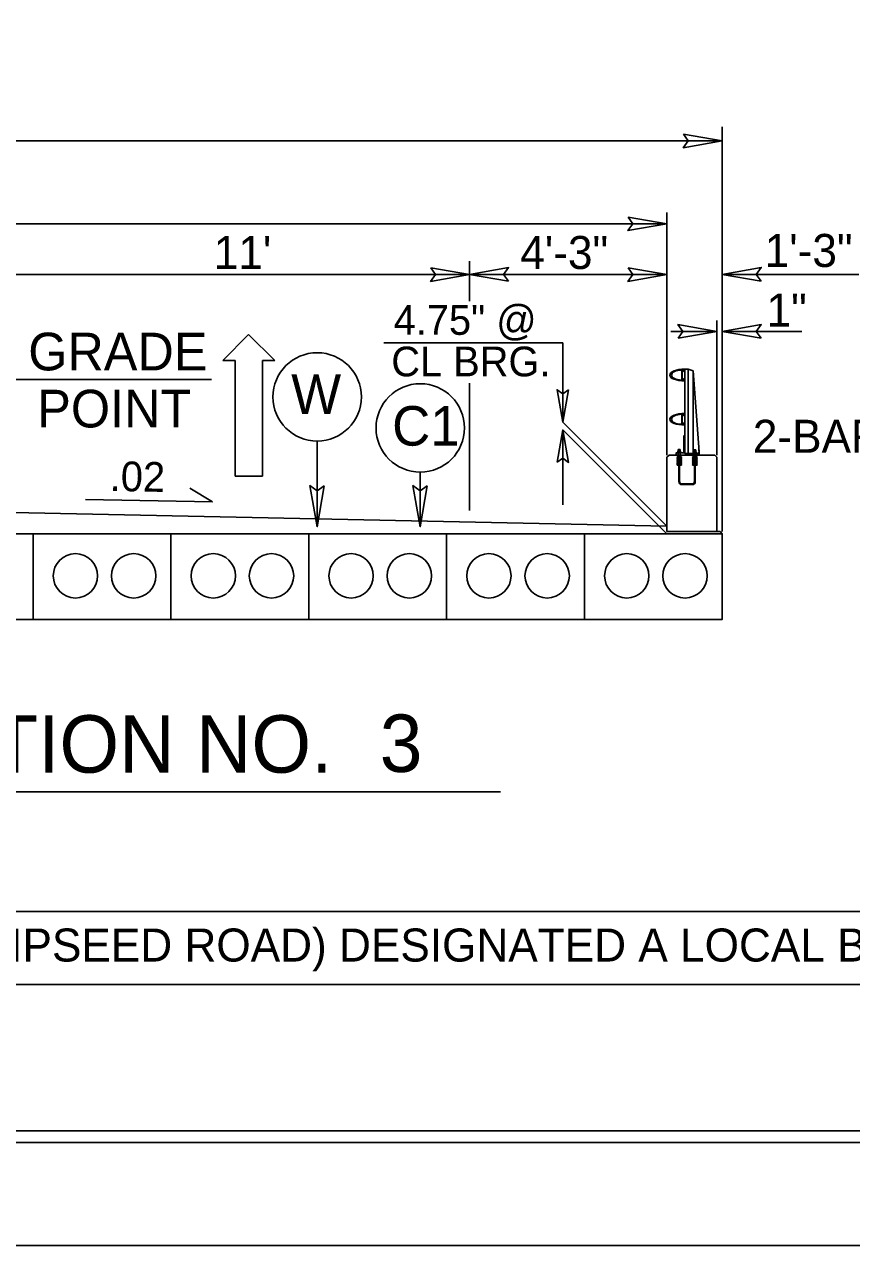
# Model space of a CAD drawing. Extents: x 693533 to 693723, y 486383 to 486493.
# Drawn here: x 693619.39 to 693637.39, y 486383.31 to 486409.89 of the extents above; entities that cross this region are included whole.
import ezdxf

# ---------------------------------------------------------------- set-up
doc = ezdxf.new("R2010")
doc.units = 0
for name, color, linetype in [('Old_Level_1', 7, 'Continuous'), ('Old_Level_28', 7, 'Continuous'), ('Old_Level_3', 7, 'Continuous'), ('Prop Dimension', 7, 'Continuous'), ('Prop Lane Arrow CELL', 7, 'Continuous'), ('Sheet Cutting Line CELL', 7, 'Continuous'), ('Sheet Plot Border Inside CELL', 7, 'Continuous'), ('Sheet Plot Border Outside CELL', 7, 'Continuous'), ('Sheet Typical CELL', 7, 'Continuous'), ('Typical Bridge Rail Two Bar CELL', 7, 'Continuous'), ('Typical ID Circle CELL', 7, 'Continuous'), ('Typical Pavement Slope Information CELL', 7, 'Continuous'), ('Typical Terminator CELL', 7, 'Continuous'), ('Typical Text ID Circle CELL', 7, 'Continuous')]:
    doc.layers.add(name, color=color, linetype=linetype)

msp = doc.modelspace()

# ---------------------------------------------------------------- linework, layer by layer
at = {"layer": 'Old_Level_1'}
msp.add_line((693607.128, 486393.188), (693629.755, 486393.188), dxfattribs=at)
msp.add_lwpolyline([(693595.018, 486390.588), (693644.204, 486390.588), (693644.204, 486388.993), (693595.018, 486388.993)], close=True, dxfattribs=at)
at = {"layer": 'Old_Level_28'}
for p, q in [((693634.581, 486398.856), (693634.581, 486407.663)), ((693601.581, 486407.359), (693634.581, 486407.359)), ((693633.374, 486400.52), (693633.374, 486405.801)), ((693602.787, 486405.557), (693633.374, 486405.557)), ((693629.081, 486403.872), (693629.081, 486404.74)), ((693618.081, 486404.451), (693629.081, 486404.451)), ((693629.081, 486404.451), (693633.374, 486404.451)), ((693634.581, 486404.454), (693637.549, 486404.454)), ((693634.464, 486400.52), (693634.464, 486403.447)), ((693634.464, 486403.211), (693633.46, 486403.211)), ((693634.581, 486403.211), (693636.31, 486403.211)), ((693619.016, 486402.168), (693623.462, 486402.168)), ((693629.081, 486399.312), (693629.081, 486402.086)), ((693618.081, 486399.291), (693633.374, 486398.972))]:
    msp.add_line(p, q, dxfattribs=at)
for points in [[(693633.737, 486407.504), (693634.581, 486407.359), (693633.732, 486407.209), (693633.84, 486407.359)], [(693632.53, 486405.702), (693633.374, 486405.557), (693632.526, 486405.407), (693632.633, 486405.557)], [(693628.237, 486404.596), (693629.081, 486404.451), (693628.232, 486404.301), (693628.34, 486404.451)], [(693629.924, 486404.305), (693629.081, 486404.451), (693629.929, 486404.601), (693629.821, 486404.451)], [(693632.53, 486404.596), (693633.374, 486404.451), (693632.526, 486404.301), (693632.633, 486404.451)], [(693635.424, 486404.308), (693634.581, 486404.454), (693635.429, 486404.604), (693635.321, 486404.454)], [(693633.62, 486403.066), (693634.464, 486403.211), (693633.615, 486403.361), (693633.723, 486403.211)], [(693635.424, 486403.066), (693634.581, 486403.211), (693635.429, 486403.361), (693635.321, 486403.211)], [(693616.581, 486398.804), (693619.581, 486398.804), (693619.581, 486396.944), (693616.581, 486396.944)], [(693619.581, 486398.804), (693622.581, 486398.804), (693622.581, 486396.944), (693619.581, 486396.944)], [(693622.581, 486398.804), (693625.581, 486398.804), (693625.581, 486396.944), (693622.581, 486396.944)], [(693625.581, 486398.804), (693628.581, 486398.804), (693628.581, 486396.944), (693625.581, 486396.944)], [(693628.581, 486398.804), (693631.581, 486398.804), (693631.581, 486396.944), (693628.581, 486396.944)], [(693631.581, 486398.804), (693634.581, 486398.804), (693634.581, 486396.944), (693631.581, 486396.944)]]:
    msp.add_lwpolyline(points, close=True, dxfattribs=at)
for centre in [(693620.501, 486397.892), (693621.769, 486397.892), (693623.501, 486397.892), (693624.769, 486397.892), (693626.501, 486397.892), (693627.769, 486397.892), (693629.501, 486397.892), (693630.769, 486397.892), (693632.501, 486397.892), (693633.769, 486397.892)]:
    msp.add_circle(centre, 0.483, dxfattribs=at)
at = {"layer": 'Prop Dimension'}
for p, q in [((693627.211, 486402.962), (693631.109, 486402.962)), ((693631.109, 486401.237), (693631.109, 486402.962)), ((693631.109, 486401.237), (693633.374, 486398.972)), ((693631.109, 486401.069), (693633.374, 486398.804)), ((693631.109, 486401.069), (693631.109, 486399.439))]:
    msp.add_line(p, q, dxfattribs=at)
at = {"layer": 'Prop Lane Arrow CELL'}
for p, q in [((693623.709, 486402.58), (693624.267, 486403.147)), ((693624.267, 486403.147), (693624.843, 486402.58)), ((693623.979, 486402.58), (693623.709, 486402.58)), ((693623.979, 486400.06), (693623.979, 486402.58)), ((693624.843, 486402.58), (693624.573, 486402.58)), ((693624.573, 486402.58), (693624.573, 486400.06)), ((693624.573, 486400.06), (693623.979, 486400.06))]:
    msp.add_line(p, q, dxfattribs=at)
at = {"layer": 'Sheet Cutting Line CELL'}
msp.add_line((693532.659, 486383.314), (693701.059, 486383.314), dxfattribs=at)
at = {"layer": 'Sheet Plot Border Inside CELL'}
msp.add_lwpolyline([(693700.609, 486491.069), (693533.959, 486491.069), (693533.959, 486385.559), (693700.609, 486385.559)], close=True, dxfattribs=at)
at = {"layer": 'Sheet Plot Border Outside CELL'}
msp.add_lwpolyline([(693701.059, 486493.314), (693532.659, 486493.314), (693532.659, 486383.314), (693701.059, 486383.314)], close=True, dxfattribs=at)
at = {"layer": 'Sheet Typical CELL'}
msp.add_lwpolyline([(693699.359, 486490.814), (693549.359, 486490.814), (693549.359, 486385.814), (693699.359, 486385.814)], close=True, dxfattribs=at)
at = {"layer": 'Typical Bridge Rail Two Bar CELL'}
for p, q in [((693633.701, 486402.362), (693633.701, 486402.262)), ((693633.763, 486402.392), (693633.836, 486402.392)), ((693633.763, 486400.557), (693633.763, 486402.392)), ((693633.947, 486402.356), (693633.836, 486402.392)), ((693633.836, 486400.557), (693633.836, 486402.392)), ((693633.947, 486400.557), (693633.947, 486402.356)), ((693633.947, 486402.356), (693634.075, 486400.593)), ((693633.701, 486402.162), (693633.701, 486402.262)), ((693633.947, 486401.514), (693633.951, 486401.514)), ((693633.701, 486401.4), (693633.701, 486401.3)), ((693633.701, 486401.2), (693633.701, 486401.3)), ((693633.422, 486400.52), (693633.374, 486400.472)), ((693633.374, 486400.472), (693633.374, 486398.856)), ((693633.422, 486400.52), (693634.416, 486400.52)), ((693633.596, 486400.485), (693633.693, 486400.485)), ((693633.596, 486400.474), (693633.693, 486400.474)), ((693633.596, 486400.441), (693633.636, 486400.441)), ((693633.596, 486400.43), (693633.636, 486400.43)), ((693633.617, 486400.463), (693633.636, 486400.463)), ((693633.617, 486400.452), (693633.636, 486400.452)), ((693633.617, 486400.419), (693633.636, 486400.419)), ((693633.617, 486400.409), (693633.636, 486400.409)), ((693633.62, 486400.485), (693633.62, 486400.566)), ((693633.622, 486400.606), (693633.622, 486400.64)), ((693633.622, 486400.64), (693633.664, 486400.64)), ((693633.636, 486400.463), (693633.652, 486400.463)), ((693633.636, 486400.463), (693633.636, 486399.946)), ((693633.652, 486400.463), (693633.671, 486400.463)), ((693633.652, 486400.463), (693633.652, 486399.946)), ((693633.652, 486400.452), (693633.671, 486400.452)), ((693633.652, 486400.441), (693633.693, 486400.441)), ((693633.652, 486400.43), (693633.693, 486400.43)), ((693633.652, 486400.419), (693633.671, 486400.419)), ((693633.652, 486400.409), (693633.671, 486400.409)), ((693633.664, 486400.64), (693633.664, 486400.606)), ((693633.666, 486400.485), (693633.666, 486400.566)), ((693633.935, 486400.485), (693634.033, 486400.485)), ((693633.935, 486400.474), (693634.033, 486400.474)), ((693633.935, 486400.441), (693633.976, 486400.441)), ((693633.935, 486400.43), (693633.976, 486400.43)), ((693633.957, 486400.463), (693633.976, 486400.463)), ((693633.957, 486400.452), (693633.976, 486400.452)), ((693633.957, 486400.419), (693633.976, 486400.419)), ((693633.957, 486400.409), (693633.976, 486400.409)), ((693633.962, 486400.596), (693633.962, 486400.631)), ((693633.962, 486400.631), (693634.003, 486400.631)), ((693633.962, 486400.475), (693633.962, 486400.557)), ((693633.976, 486400.463), (693633.992, 486400.463)), ((693633.976, 486400.463), (693633.976, 486399.946)), ((693633.992, 486400.463), (693634.011, 486400.463)), ((693633.992, 486400.463), (693633.992, 486399.946)), ((693633.992, 486400.452), (693634.011, 486400.452)), ((693633.992, 486400.441), (693634.033, 486400.441)), ((693633.992, 486400.43), (693634.033, 486400.43)), ((693633.992, 486400.419), (693634.011, 486400.419)), ((693633.992, 486400.409), (693634.011, 486400.409)), ((693634.003, 486400.631), (693634.003, 486400.596)), ((693634.004, 486400.475), (693634.004, 486400.557)), ((693634.072, 486400.614), (693634.072, 486400.646)), ((693634.075, 486400.557), (693634.075, 486400.593)), ((693634.464, 486400.472), (693634.416, 486400.52)), ((693634.464, 486400.472), (693634.464, 486398.856)), ((693633.596, 486400.398), (693633.636, 486400.398)), ((693633.596, 486400.387), (693633.636, 486400.387)), ((693633.596, 486400.355), (693633.636, 486400.355)), ((693633.596, 486400.344), (693633.636, 486400.344)), ((693633.596, 486400.311), (693633.636, 486400.311)), ((693633.596, 486400.301), (693633.636, 486400.301)), ((693633.617, 486400.376), (693633.636, 486400.376)), ((693633.617, 486400.365), (693633.636, 486400.365)), ((693633.617, 486400.333), (693633.636, 486400.333)), ((693633.617, 486400.322), (693633.636, 486400.322)), ((693633.652, 486400.398), (693633.693, 486400.398)), ((693633.652, 486400.387), (693633.693, 486400.387)), ((693633.652, 486400.376), (693633.671, 486400.376)), ((693633.652, 486400.365), (693633.671, 486400.365)), ((693633.652, 486400.355), (693633.693, 486400.355)), ((693633.652, 486400.344), (693633.693, 486400.344)), ((693633.652, 486400.333), (693633.671, 486400.333)), ((693633.652, 486400.322), (693633.671, 486400.322)), ((693633.652, 486400.311), (693633.693, 486400.311)), ((693633.652, 486400.301), (693633.693, 486400.301)), ((693633.935, 486400.398), (693633.976, 486400.398)), ((693633.935, 486400.387), (693633.976, 486400.387)), ((693633.935, 486400.355), (693633.976, 486400.355)), ((693633.935, 486400.344), (693633.976, 486400.344)), ((693633.935, 486400.311), (693633.976, 486400.311)), ((693633.935, 486400.301), (693633.976, 486400.301)), ((693633.957, 486400.376), (693633.976, 486400.376)), ((693633.957, 486400.365), (693633.976, 486400.365)), ((693633.957, 486400.333), (693633.976, 486400.333)), ((693633.957, 486400.322), (693633.976, 486400.322)), ((693633.992, 486400.398), (693634.033, 486400.398)), ((693633.992, 486400.387), (693634.033, 486400.387)), ((693633.992, 486400.376), (693634.011, 486400.376)), ((693633.992, 486400.365), (693634.011, 486400.365)), ((693633.992, 486400.355), (693634.033, 486400.355)), ((693633.992, 486400.344), (693634.033, 486400.344)), ((693633.992, 486400.333), (693634.011, 486400.333)), ((693633.992, 486400.322), (693634.011, 486400.322)), ((693633.992, 486400.311), (693634.033, 486400.311)), ((693633.992, 486400.301), (693634.033, 486400.301)), ((693633.704, 486399.894), (693633.924, 486399.894)), ((693633.704, 486399.878), (693633.924, 486399.878)), ((693633.374, 486398.856), (693634.454, 486398.856)), ((693634.454, 486398.856), (693634.533, 486398.856)), ((693634.581, 486398.804), (693634.533, 486398.856))]:
    msp.add_line(p, q, dxfattribs=at)
for points in [[(693633.763, 486402.135), (693633.763, 486402.182), (693633.743, 486402.182), (693633.743, 486402.175), (693633.745, 486402.175), (693633.745, 486402.155), (693633.713, 486402.155), (693633.709, 486402.185), (693633.709, 486402.262), (693633.709, 486402.339), (693633.713, 486402.369), (693633.745, 486402.369), (693633.745, 486402.349), (693633.743, 486402.349), (693633.743, 486402.341), (693633.763, 486402.341), (693633.763, 486402.389)], [(693633.763, 486401.173), (693633.763, 486401.221), (693633.743, 486401.221), (693633.743, 486401.213), (693633.745, 486401.213), (693633.745, 486401.193), (693633.713, 486401.193), (693633.709, 486401.223), (693633.709, 486401.3), (693633.709, 486401.377), (693633.713, 486401.407), (693633.745, 486401.407), (693633.745, 486401.388), (693633.743, 486401.388), (693633.743, 486401.38), (693633.763, 486401.38), (693633.763, 486401.427)], [(693633.574, 486400.52), (693633.574, 486400.566), (693633.744, 486400.566), (693633.744, 486400.942), (693633.763, 486400.942), (693633.763, 486400.557), (693634.066, 486400.557), (693634.066, 486400.584), (693634.075, 486400.584), (693634.075, 486400.52), (693633.929, 486400.52), (693633.929, 486400.545), (693633.781, 486400.545), (693633.781, 486400.52), (693633.574, 486400.52)], [(693633.595, 486400.485), (693633.595, 486400.474), (693633.617, 486400.463), (693633.617, 486400.452), (693633.595, 486400.441), (693633.595, 486400.43), (693633.617, 486400.419), (693633.617, 486400.409), (693633.595, 486400.398), (693633.595, 486400.387), (693633.617, 486400.376), (693633.617, 486400.365), (693633.595, 486400.355), (693633.595, 486400.344), (693633.617, 486400.333), (693633.617, 486400.322), (693633.595, 486400.311), (693633.595, 486400.301)], [(693633.6, 486400.566), (693633.6, 486400.574), (693633.642, 486400.574), (693633.684, 486400.574), (693633.684, 486400.566)], [(693633.612, 486400.574), (693633.612, 486400.6), (693633.617, 486400.605), (693633.669, 486400.605), (693633.674, 486400.6), (693633.674, 486400.574), (693633.612, 486400.574), (693633.633, 486400.574), (693633.633, 486400.6), (693633.627, 486400.605), (693633.633, 486400.6), (693633.638, 486400.605), (693633.648, 486400.605), (693633.653, 486400.6), (693633.653, 486400.574), (693633.653, 486400.6), (693633.658, 486400.605)], [(693633.693, 486400.485), (693633.693, 486400.474), (693633.671, 486400.463), (693633.671, 486400.452), (693633.693, 486400.441), (693633.693, 486400.43), (693633.671, 486400.419), (693633.671, 486400.409), (693633.693, 486400.398), (693633.693, 486400.387), (693633.671, 486400.376), (693633.671, 486400.365), (693633.693, 486400.355), (693633.693, 486400.344), (693633.671, 486400.333), (693633.671, 486400.322), (693633.693, 486400.311), (693633.693, 486400.301)], [(693633.935, 486400.485), (693633.935, 486400.474), (693633.956, 486400.463), (693633.956, 486400.452), (693633.935, 486400.441), (693633.935, 486400.43), (693633.956, 486400.419), (693633.956, 486400.409), (693633.935, 486400.398), (693633.935, 486400.387), (693633.956, 486400.376), (693633.956, 486400.365), (693633.935, 486400.355), (693633.935, 486400.344), (693633.956, 486400.333), (693633.956, 486400.322), (693633.935, 486400.311), (693633.935, 486400.301)], [(693633.941, 486400.556), (693633.941, 486400.564), (693633.983, 486400.564), (693634.025, 486400.564), (693634.025, 486400.556)], [(693633.952, 486400.564), (693633.952, 486400.591), (693633.957, 486400.596), (693634.008, 486400.596), (693634.014, 486400.591), (693634.014, 486400.564), (693633.952, 486400.564), (693633.972, 486400.564), (693633.972, 486400.591), (693633.967, 486400.596), (693633.972, 486400.591), (693633.977, 486400.596), (693633.988, 486400.596), (693633.993, 486400.591), (693633.993, 486400.564), (693633.993, 486400.591), (693633.999, 486400.596)], [(693634.033, 486400.485), (693634.033, 486400.474), (693634.011, 486400.463), (693634.011, 486400.452), (693634.033, 486400.441), (693634.033, 486400.43), (693634.011, 486400.419), (693634.011, 486400.409), (693634.033, 486400.398), (693634.033, 486400.387), (693634.011, 486400.376), (693634.011, 486400.365), (693634.033, 486400.355), (693634.033, 486400.344), (693634.011, 486400.333), (693634.011, 486400.322), (693634.033, 486400.311), (693634.033, 486400.301)]]:
    msp.add_lwpolyline(points, dxfattribs=at)
for centre in [(693633.604, 486400.327), (693634.024, 486400.327)]:
    msp.add_circle(centre, 0.00813, dxfattribs=at)
for centre, radius, start, end in [((693633.693, 486402.362), 0.00763, 0, 90), ((693633.693, 486402.162), 0.00763, 270, 0), ((693633.693, 486401.4), 0.00763, 0, 90), ((693633.693, 486401.2), 0.00763, 270, 0), ((693633.704, 486399.946), 0.0683, 180, 270), ((693633.704, 486399.946), 0.052, 180, 270), ((693633.924, 486399.946), 0.052, 270, 0), ((693633.924, 486399.946), 0.0683, 270, 0)]:
    msp.add_arc(centre, radius, start, end, dxfattribs=at)
for centre, major_axis, ratio, start_param, end_param in [((693633.763, 486402.262), (-0.326, 0), 0.39036, 4.712404, 6.283584), ((693633.693, 486402.262), (-0.217, 0), 0.495501, 4.712489, 6.283652), ((693633.763, 486402.262), (-0.326, 0), 0.39036, 0.000398, 1.570782), ((693633.693, 486402.262), (-0.217, 0), 0.495501, 0.000467, 1.570696), ((693633.763, 486401.3), (-0.326, 0), 0.39036, 4.712404, 6.283584), ((693633.763, 486401.3), (-0.326, 0), 0.39036, 0.000398, 1.570782), ((693633.693, 486401.3), (-0.217, 0), 0.495501, 4.712489, 6.283652), ((693633.693, 486401.3), (-0.217, 0), 0.495501, 0.000467, 1.570696)]:
    msp.add_ellipse(centre, major_axis=major_axis, ratio=ratio, start_param=start_param, end_param=end_param, dxfattribs=at)
at = {"layer": 'Typical ID Circle CELL'}
for p, q in [((693625.763, 486400.825), (693625.763, 486398.959)), ((693628.006, 486400.149), (693628.006, 486398.962))]:
    msp.add_line(p, q, dxfattribs=at)
for centre in [(693625.763, 486401.787), (693628.006, 486401.111)]:
    msp.add_circle(centre, 0.962, dxfattribs=at)
at = {"layer": 'Typical Pavement Slope Information CELL'}
for q in [(693622.991, 486399.801), (693620.722, 486399.556)]:
    msp.add_line((693623.487, 486399.501), q, dxfattribs=at)
at = {"layer": 'Typical Terminator CELL'}
for points in [[(693631.23, 486401.94), (693631.109, 486401.237), (693630.984, 486401.944), (693631.109, 486401.854)], [(693630.988, 486400.366), (693631.109, 486401.069), (693631.234, 486400.362), (693631.109, 486400.452)], [(693625.917, 486399.85), (693625.763, 486398.959), (693625.605, 486399.855), (693625.763, 486399.741)], [(693628.159, 486399.853), (693628.006, 486398.962), (693627.848, 486399.858), (693628.006, 486399.744)]]:
    msp.add_lwpolyline(points, close=True, dxfattribs=at)

# ---------------------------------------------------------------- texts
at = {"layer": 'Old_Level_28'}
for s, height, p in [("11'", 0.7188, (693623.512, 486404.571)), ('4\'-3"', 0.7188, (693630.183, 486404.571)), ('1\'-3"', 0.7188, (693635.503, 486404.615)), ('1"', 0.7188, (693635.544, 486403.318)), ('GRADE', 0.82, (693619.474, 486402.364)), ('POINT', 0.82, (693619.671, 486401.122))]:
    msp.add_text(s, height=height, dxfattribs=at).set_placement(p)
for s, p in [('2-BAR METAL RAIL', (693635.246, 486400.57)), ('NOTE: TOWN OF KNIGHTDALE HAS SR 2507 (TURNIPSEED ROAD) DESIGNATED A LOCAL BIKE ROUTE.', (693595.424, 486389.496))]:
    msp.add_text(s, height=0.71875, rotation=360, dxfattribs=at).set_placement(p)
at = {"layer": 'Old_Level_3'}
for s, p in [('TYPICAL SECTION NO.  ', (693607.799, 486393.607)), ('3', (693627.124, 486393.623))]:
    msp.add_text(s, height=1.25, dxfattribs=at).set_placement(p)
at = {"layer": 'Prop Dimension'}
for s, p in [('4.75" @', (693627.427, 486403.138)), ('CL BRG.', (693627.376, 486402.234))]:
    msp.add_text(s, height=0.6476, rotation=360, dxfattribs=at).set_placement(p)
at = {"layer": 'Typical Pavement Slope Information CELL'}
msp.add_text('.02', height=0.6476, rotation=358.8543, dxfattribs=at).set_placement((693621.242, 486399.741))
at = {"layer": 'Typical Text ID Circle CELL'}
for s, height, p in [('W', 0.861, (693625.197, 486401.416)), ('C1', 0.8608, (693627.394, 486400.726))]:
    msp.add_text(s, height=height, dxfattribs=at).set_placement(p)

doc.saveas('drawing.dxf')
